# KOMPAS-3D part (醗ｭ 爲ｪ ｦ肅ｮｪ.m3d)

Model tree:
1. Эскиз:1
2. Операция выдавливания:1
     Расстояние 1 = 37
3. Эскиз:2
4. Операция выдавливания:2
     Расстояние 1 = 4
5. Эскиз:3
6. Операция выдавливания:3
     Расстояние 1 = 5
7. Эскиз:5
8. Операция выдавливания:4
     Расстояние 1 = 4
9. Фаска:1
     Угол = 45; Длина 1 = 1; Длина 2 = 1
10. Фаска:2
     Угол = 45; Длина 1 = 1; Длина 2 = 1
11. Фаска:4
     Угол = 45; Длина 1 = 1.5; Длина 2 = 1.5
